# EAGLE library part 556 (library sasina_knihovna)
Casovac 556 coz jsou dva casovace 555 v jednom pouzdru.
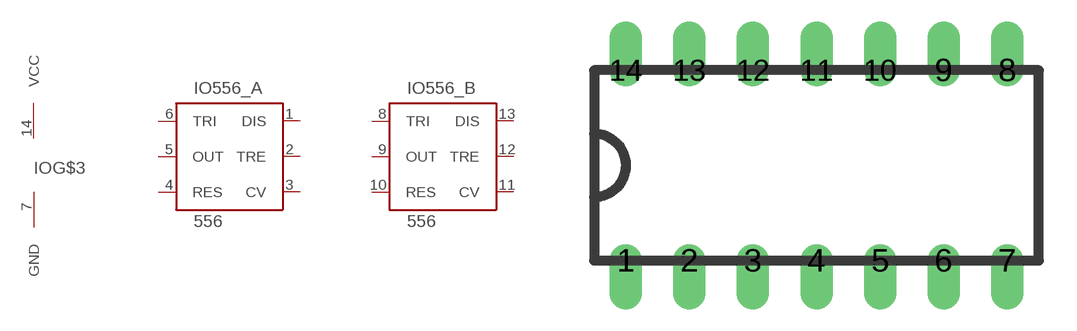
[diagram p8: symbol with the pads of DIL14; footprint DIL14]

Designator prefix IO; gates 556_A=556 556_B=556 G$3=NAPAJENI

## 556N  [DIL14]
1  556_A:DIS  out
2  556_A:TRE  in
3  556_A:CV  pas
4  556_A:RES  in
5  556_A:OUT  out
6  556_A:TRI  in
7  G$3:GND  pwr
8  556_B:TRI  in
9  556_B:OUT  out
10  556_B:RES  in
11  556_B:CV  pas
12  556_B:TRE  in
13  556_B:DIS  out
14  G$3:VCC  pwr

## 556D  [DIL14]
Pads as for DIL14

## Footprint DIL14 (pad centres in mm)
drill 0.8 offset: 1 0,-1.27; 2 2.54,-1.27; 3 5.08,-1.27; 4 7.62,-1.27; 5 10.16,-1.27; 6 12.7,-1.27; 7 15.24,-1.27; 8 15.24,6.35; 9 12.7,6.35; 10 10.16,6.35; 11 7.62,6.35; 12 5.08,6.35; 13 2.54,6.35; 14 0,6.35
